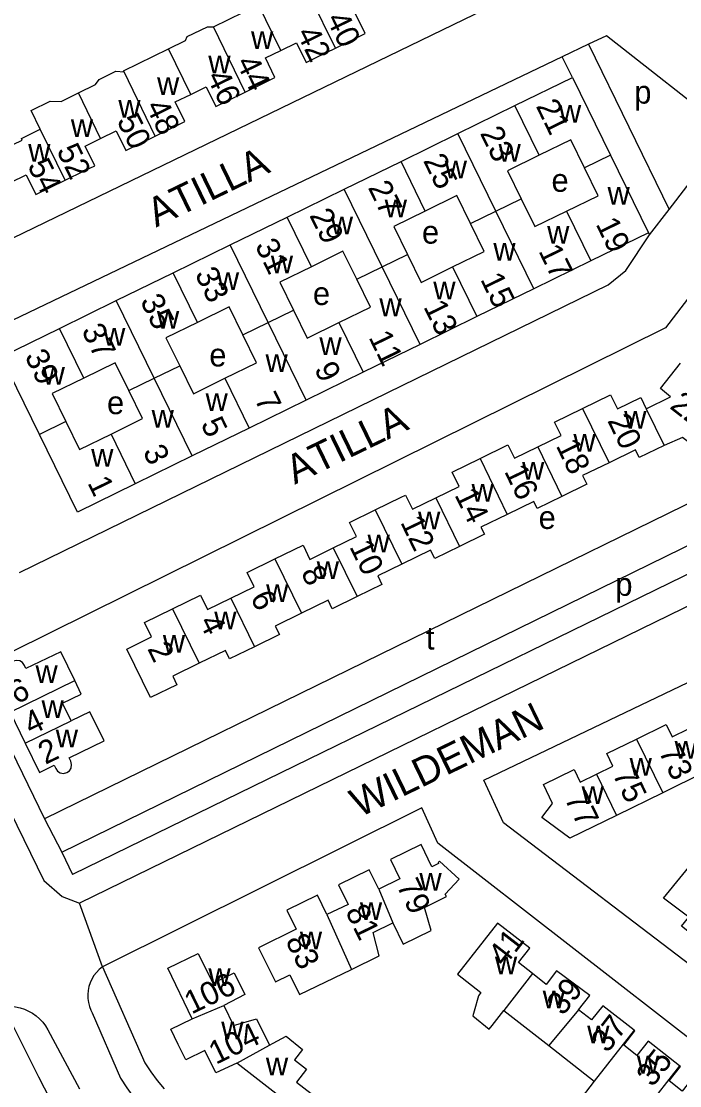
# Model space of a CAD drawing. Extents: x 159441 to 162086, y 388175 to 389787.
# Drawn here: x 161483.8 to 161598.1, y 388970.9 to 389155.6 of the extents above; entities that cross this region are included whole.
import ezdxf

# ---------------------------------------------------------------- set-up
doc = ezdxf.new("R2010")
doc.units = 0
for name, color, linetype in [('BLT_Basislijn', 7, 'Continuous'), ('BLT_Bebouwing', 7, 'Continuous'), ('BLT_Centroide', 7, 'Continuous'), ('BLT_Huisnummer', 7, 'Continuous'), ('BLT_Huisnummer_ tussenligend', 7, 'Continuous'), ('BLT_Onderverdeling_panden', 7, 'Continuous'), ('BLT_Straatnaam', 7, 'Continuous'), ('BLT_Vlakafsluiter', 7, 'Continuous')]:
    doc.layers.add(name, color=color, linetype=linetype)

msp = doc.modelspace()

# ---------------------------------------------------------------- linework, layer by layer
at = {"layer": 'BLT_Basislijn'}
for p, q in [((161582.29, 389151.56), (161577.7, 389149.36)), ((161582.29, 389151.56), (161596.3, 389122.92)), ((161579.53, 389145.82), (161577.7, 389149.36)), ((161592.9, 389118.5), (161596.3, 389122.92)), ((161592.71, 389118.87), (161592.9, 389118.5)), ((161564.11, 389023.88), (161624.74, 389052.92)), ((161567.55, 389016.49), (161564.11, 389023.88)), ((161553.38, 389019.06), (161497.93, 388991.48)), ((161556.12, 389012.95), (161553.38, 389019.06)), ((161669.17, 388938.91), (161567.55, 389016.49)), ((161661.19, 388931.3), (161556.12, 389012.95)), ((161497.93, 388991.48), (161505.28, 388974.84)), ((161486.88, 388972.34), (161480.76, 388984.58)), ((161496.17, 388983.5), (161501.07, 388972.14)), ((161488.48, 388980.54), (161493.94, 388970.29)), ((161505.28, 388974.84), (161506.33, 388973.28)), ((161506.33, 388973.28), (161507.44, 388971.77)), ((161507.44, 388971.77), (161508.62, 388970.3))]:
    msp.add_line(p, q, dxfattribs=at)
for points in [[(161431.36, 389153.61), (161423.06, 389149.55), (161446.94, 389100.8), (161584.9, 389167.69)], [(161596.3, 389122.92), (161606.62, 389136.37), (161585.4, 389153.05), (161582.29, 389151.56)], [(161577.7, 389149.36), (161465.43, 389095.59)], [(161623.83, 389139.1), (161595.65, 389102.37), (161475.36, 389042.81), (161487.87, 389017.18)], [(161647.2, 389120.24), (161615.5, 389079.64), (161487.87, 389017.18)], [(161483.54, 389059.9), (161585.71, 389109.81), (161588.75, 389112.33), (161592.9, 389118.5)], [(161490.89, 389011.37), (161618.3, 389073.8), (161620.71, 389075.73), (161652.36, 389115.82)], [(161655.94, 389112.75), (161625.53, 389073.89), (161617.95, 389068.61), (161492.72, 389007.49)], [(161618.18, 389063.15), (161493.93, 389002.52)], [(161471.42, 389039.92), (161487.78, 389006.47), (161490.93, 389003.71), (161493.93, 389002.52)], [(161487.87, 389017.18), (161490.89, 389011.37)], [(161490.89, 389011.37), (161492.72, 389007.49)], [(161497.93, 388991.48), (161497.37, 388991.02), (161496.88, 388990.52), (161496.46, 388989.96), (161496.09, 388989.36), (161495.8, 388988.72), (161495.59, 388988.05), (161495.45, 388987.37), (161495.39, 388986.67), (161495.41, 388985.97), (161495.51, 388985.28), (161495.69, 388984.6), (161495.94, 388983.95), (161496.17, 388983.5)], [(161480.76, 388984.58), (161481.28, 388984.63), (161482.07, 388984.62), (161482.86, 388984.54), (161483.63, 388984.37), (161484.38, 388984.12), (161485.1, 388983.81), (161485.79, 388983.42), (161486.44, 388982.96), (161487.03, 388982.44), (161487.57, 388981.86), (161488.05, 388981.23), (161488.48, 388980.54)], [(161500.72, 388954.39), (161499.17, 388955.75), (161497.67, 388957.17), (161496.22, 388958.65), (161494.84, 388960.18), (161493.51, 388961.77), (161492.24, 388963.41), (161491.05, 388965.09), (161489.91, 388966.82), (161488.85, 388968.59), (161487.85, 388970.4), (161486.88, 388972.34)], [(161501.07, 388972.14), (161502.18, 388970.49), (161503.35, 388968.89), (161504.58, 388967.33), (161505.88, 388965.83), (161507.24, 388964.38), (161508.65, 388962.99), (161510.12, 388961.65), (161511.2, 388960.73)]]:
    msp.add_lwpolyline(points, dxfattribs=at)
at = {"layer": 'BLT_Bebouwing'}
for p, q in [((161559.63, 389136.09), (161569.51, 389140.92)), ((161549.75, 389131.25), (161559.63, 389136.09)), ((161539.87, 389126.42), (161549.75, 389131.25)), ((161529.99, 389121.59), (161539.87, 389126.42)), ((161520.1, 389116.75), (161529.99, 389121.59)), ((161510.22, 389111.92), (161520.1, 389116.75)), ((161582.69, 389113.97), (161572.81, 389109.14)), ((161500.34, 389107.09), (161510.22, 389111.92)), ((161572.81, 389109.14), (161562.93, 389104.31)), ((161490.46, 389102.25), (161500.34, 389107.09)), ((161562.93, 389104.31), (161553.05, 389099.47)), ((161480.41, 389097.34), (161490.46, 389102.25)), ((161553.05, 389099.47), (161543.17, 389094.64)), ((161487, 389083.86), (161480.41, 389097.34)), ((161543.17, 389094.64), (161533.29, 389089.81)), ((161533.29, 389089.81), (161523.41, 389084.97)), ((161523.41, 389084.97), (161513.52, 389080.14)), ((161513.52, 389080.14), (161503.64, 389075.31)), ((161481.93, 389035.66), (161484.54, 389030.27)), ((161603.18, 389025.66), (161595.17, 389021.68)), ((161595.17, 389021.68), (161587.17, 389017.76)), ((161567.61, 388983.89), (161575.39, 388977.8)), ((161575.39, 388977.8), (161583.28, 388971.62))]:
    msp.add_line(p, q, dxfattribs=at)
for points in [[(161517.21, 389154.58), (161525.02, 389158.4)], [(161538.37, 389150.91), (161543.52, 389153.43), (161541.85, 389156.85), (161544.52, 389158.15)], [(161509.39, 389150.76), (161512.37, 389152.22), (161512.65, 389152.9), (161516.18, 389154.58), (161517.21, 389154.58)], [(161528.88, 389150.5), (161531.6, 389151.83), (161533.27, 389148.42), (161535.14, 389149.34), (161538.37, 389150.91)], [(161501.7, 389146.77), (161501.61, 389146.96), (161509.39, 389150.76)], [(161522.73, 389143.27), (161526.01, 389144.87), (161527.88, 389145.79), (161526.21, 389149.2), (161528.88, 389150.5)], [(161493.76, 389143.11), (161496.74, 389144.57), (161497.36, 389145.44), (161500.24, 389146.88), (161501.7, 389146.77)], [(161569.51, 389140.92), (161579.53, 389145.82)], [(161579.53, 389145.82), (161586.12, 389132.35)], [(161513.25, 389142.86), (161515.96, 389144.19), (161517.63, 389140.77), (161519.5, 389141.69), (161522.73, 389143.27)], [(161487.13, 389136.83), (161485.54, 389140.07), (161488.84, 389141.69), (161490.77, 389141.65), (161493.76, 389143.11)], [(161507.1, 389135.62), (161510.38, 389137.23), (161512.24, 389138.14), (161510.58, 389141.55), (161513.25, 389142.86)], [(161478.12, 389135.47), (161481.1, 389136.92), (161482.44, 389134.18), (161484.02, 389134.95), (161483.88, 389135.24), (161487.13, 389136.83)], [(161497.62, 389135.22), (161500.33, 389136.54), (161502, 389133.13), (161507.1, 389135.62)], [(161491.47, 389127.98), (161494.74, 389129.58), (161496.61, 389130.49), (161494.94, 389133.9), (161497.62, 389135.22)], [(161581.58, 389130.13), (161579.21, 389134.98), (161573.73, 389132.3)], [(161573.73, 389132.3), (161568.25, 389129.62), (161570.62, 389124.77)], [(161586.12, 389132.35), (161592.71, 389118.87)], [(161578.48, 389122.6), (161583.95, 389125.28), (161581.58, 389130.13)], [(161481.99, 389127.57), (161484.69, 389128.89), (161486.36, 389125.48), (161491.47, 389127.98)], [(161561.82, 389120.46), (161559.45, 389125.31), (161553.97, 389122.63)], [(161570.62, 389124.77), (161573, 389119.92), (161578.48, 389122.6)], [(161553.97, 389122.63), (161548.49, 389119.95), (161550.86, 389115.1)], [(161558.71, 389112.93), (161564.19, 389115.61), (161561.82, 389120.46)], [(161592.71, 389118.87), (161582.69, 389113.97)], [(161542.06, 389110.79), (161539.68, 389115.64), (161534.2, 389112.96)], [(161550.86, 389115.1), (161553.23, 389110.25), (161558.71, 389112.93)], [(161534.2, 389112.96), (161528.73, 389110.28), (161531.1, 389105.43)], [(161538.95, 389103.26), (161544.43, 389105.94), (161542.06, 389110.79)], [(161522.29, 389101.13), (161519.92, 389105.98), (161514.44, 389103.3)], [(161531.1, 389105.43), (161533.47, 389100.58), (161538.95, 389103.26)], [(161514.44, 389103.3), (161508.96, 389100.62), (161511.34, 389095.77)], [(161519.19, 389093.6), (161524.67, 389096.28), (161522.29, 389101.13)], [(161502.53, 389091.46), (161500.16, 389096.31), (161494.68, 389093.63)], [(161511.34, 389095.77), (161513.71, 389090.92), (161519.19, 389093.6)], [(161592.32, 389088.29), (161596.53, 389090.37), (161594.78, 389091.81), (161598.25, 389096.25)], [(161494.68, 389093.63), (161489.2, 389090.95), (161491.57, 389086.1)], [(161499.43, 389083.93), (161504.9, 389086.61), (161502.53, 389091.46)], [(161581.24, 389088.38), (161586.1, 389090.75), (161587.3, 389088.28), (161591.35, 389090.26), (161592.32, 389088.29)], [(161573.48, 389081.72), (161577.53, 389083.69), (161576.39, 389086.01), (161581.24, 389088.38)], [(161606.52, 389089.79), (161603.67, 389086.14), (161604.94, 389085.15), (161601.66, 389080.95), (161598.62, 389083.33), (161595.4, 389081.97)], [(161491.57, 389086.1), (161493.95, 389081.25), (161499.43, 389083.93)], [(161503.64, 389075.31), (161493.59, 389070.39), (161487, 389083.86)], [(161563.46, 389079.68), (161568.31, 389082.05), (161569.44, 389079.74), (161573.48, 389081.72)], [(161595.4, 389081.97), (161591.09, 389079.86), (161590.44, 389081.19), (161585.85, 389078.95)], [(161555.77, 389072.86), (161559.82, 389074.84), (161558.61, 389077.31), (161563.46, 389079.68)], [(161585.85, 389078.95), (161581.27, 389076.71), (161582, 389075.23), (161577.68, 389073.12)], [(161545.29, 389070.8), (161549.77, 389072.99), (161550.52, 389073.35), (161551.73, 389070.88), (161555.77, 389072.86)], [(161577.68, 389073.12), (161573.38, 389071.01), (161572.78, 389072.23), (161568.2, 389069.99)], [(161537.99, 389064.16), (161542.03, 389066.14), (161540.82, 389068.61), (161545.29, 389070.8)], [(161568.2, 389069.99), (161563.62, 389067.75), (161564.21, 389066.53), (161559.9, 389064.42)], [(161527.88, 389062.28), (161532.74, 389064.65), (161533.94, 389062.18), (161537.99, 389064.16)], [(161559.9, 389064.42), (161555.59, 389062.32), (161554.87, 389063.79), (161549.9, 389061.37)], [(161520.2, 389055.46), (161524.24, 389057.44), (161523.03, 389059.91), (161527.88, 389062.28)], [(161549.9, 389061.37), (161545.7, 389059.32), (161546.43, 389057.83), (161542.12, 389055.72)], [(161510.1, 389053.58), (161514.95, 389055.95), (161516.16, 389053.48), (161520.2, 389055.46)], [(161542.12, 389055.72), (161537.8, 389053.61), (161537.08, 389055.09), (161532.5, 389052.85)], [(161514.71, 389044.15), (161510.13, 389041.92), (161510.85, 389040.43), (161506.27, 389038.19), (161502.15, 389046.63), (161506.46, 389048.74), (161505.25, 389051.21), (161510.1, 389053.58)], [(161532.5, 389052.85), (161527.91, 389050.62), (161528.64, 389049.13), (161524.33, 389047.02)], [(161493.13, 389041.14), (161490.7, 389046.16), (161484.65, 389043.24), (161484.39, 389043.78), (161484.05, 389044.27), (161483.6, 389044.56), (161483.02, 389044.66), (161482.43, 389044.51), (161481.92, 389044.1), (161481.66, 389043.57), (161481.63, 389043.01), (161481.79, 389042.52), (161482.05, 389041.98), (161479.48, 389040.73)], [(161524.33, 389047.02), (161520.01, 389044.91), (161519.29, 389046.39), (161514.71, 389044.15)], [(161492.51, 389034.15), (161491.01, 389037.24), (161494.25, 389038.82), (161493.13, 389041.14)], [(161484.54, 389030.27), (161486.99, 389025.2), (161489.56, 389026.45), (161489.82, 389025.91), (161490.13, 389025.45), (161490.58, 389025.15), (161491.15, 389025.03), (161491.78, 389025.18), (161492.21, 389025.49), (161492.49, 389025.94), (161492.59, 389026.57), (161492.42, 389027.18), (161492.16, 389027.72), (161498.22, 389030.67), (161495.75, 389035.74), (161492.51, 389034.15)], [(161590.61, 389031), (161595.76, 389033.53), (161596.83, 389031.37), (161599.66, 389032.76)], [(161583.67, 389024.93), (161586.51, 389026.32), (161585.45, 389028.47), (161590.61, 389031)], [(161587.17, 389017.76), (161579.05, 389013.79), (161574.2, 389017.37), (161576.04, 389019.83), (161574.46, 389023.09), (161579.78, 389025.7), (161580.83, 389023.54), (161583.67, 389024.93)], [(161548.34, 388999.12), (161550.14, 388995.42), (161554.98, 388997.79), (161553.83, 389001.8), (161557.63, 389003.66), (161557.41, 389004.1), (161559.83, 389006.69), (161556.4, 389009.82), (161556.18, 389009.59), (161556.27, 389009.41), (161555.1, 389008.84), (161553.22, 389012.69), (161547.9, 389010.08), (161549.55, 389006.74), (161545.89, 389004.95)], [(161602.29, 388995.48), (161598.42, 388998.53), (161599.7, 389000.09), (161595.32, 389003.42), (161602, 389011.58), (161606.38, 389008.15), (161607.25, 389009.27), (161610.91, 389006.44)], [(161545.89, 389004.95), (161544.24, 389008.29), (161538.91, 389005.69), (161540.59, 389002.32), (161536.88, 389000.54)], [(161536.88, 389000.54), (161535.26, 389003.92), (161529.96, 389001.29), (161531.56, 388997.99), (161525.04, 388994.8), (161527.94, 388988.87), (161530.48, 388990.11), (161532.16, 388986.65), (161541.14, 388991.04)], [(161541.14, 388991.04), (161545.98, 388993.4), (161544.93, 388997.45), (161548.34, 388999.12)], [(161572.56, 388990.31), (161570.12, 388992.22), (161572.08, 388994.69), (161566.49, 388999.07), (161559.53, 388990.22), (161563.61, 388987.03), (161563.17, 388986.46), (161562.46, 388983.78), (161562.23, 388982.96), (161565.07, 388980.67), (161565.59, 388981.32), (161567.61, 388983.89)], [(161513.48, 388982.48), (161509.26, 388991.22), (161514.57, 388993.81), (161517.09, 388988.65), (161520.77, 388990.44), (161522.62, 388986.65), (161518.98, 388984.76)], [(161580.55, 388984.04), (161582.5, 388986.52), (161576.71, 388990.77), (161574.96, 388988.43), (161572.56, 388990.31)], [(161518.98, 388984.76), (161520.68, 388981.29), (161524.68, 388982.43), (161526.9, 388977.91)], [(161590.23, 388980.47), (161584.77, 388984.73), (161582.83, 388982.26), (161580.55, 388984.04)], [(161511.09, 388978.01), (161509.79, 388980.67), (161513.48, 388982.48)], [(161526.9, 388977.91), (161527.55, 388978.26), (161529.82, 388979.47)], [(161529.82, 388979.47), (161532.65, 388977.12), (161531.27, 388975.36), (161533.37, 388973.72), (161531.62, 388971.48), (161536.17, 388967.93)], [(161598.09, 388974.3), (161592.64, 388978.57), (161590.7, 388976.09), (161588.4, 388977.89), (161590.35, 388980.37), (161590.23, 388980.47)], [(161521.27, 388974.74), (161517.62, 388973.07), (161515.72, 388976.97), (161512.4, 388975.34), (161511.09, 388978.01)], [(161529.98, 388960.03), (161525.26, 388963.73), (161529.07, 388968.68), (161521.27, 388974.74)], [(161605.96, 388968.13), (161600.5, 388972.39), (161598.56, 388969.92), (161596.29, 388971.71), (161598.23, 388974.18), (161598.09, 388974.3)], [(161583.28, 388971.62), (161580.41, 388967.95), (161583.53, 388965.51), (161586.13, 388965.77), (161587.88, 388968.01), (161591.15, 388965.45)]]:
    msp.add_lwpolyline(points, dxfattribs=at)
at = {"layer": 'BLT_Onderverdeling_panden'}
for p, q in [((161538.37, 389150.91), (161532.83, 389162.22)), ((161528.88, 389150.5), (161525.02, 389158.4)), ((161522.73, 389143.27), (161517.21, 389154.58)), ((161513.25, 389142.86), (161509.39, 389150.76)), ((161507.1, 389135.62), (161501.7, 389146.77)), ((161497.62, 389135.22), (161493.76, 389143.11)), ((161573.73, 389132.3), (161569.51, 389140.92)), ((161491.47, 389127.98), (161487.13, 389136.83)), ((161566.22, 389122.61), (161559.63, 389136.09)), ((161553.97, 389122.63), (161549.75, 389131.25)), ((161586.12, 389132.35), (161581.58, 389130.13)), ((161546.46, 389112.95), (161539.87, 389126.42)), ((161566.22, 389122.61), (161570.62, 389124.77)), ((161534.2, 389112.96), (161529.99, 389121.59)), ((161561.82, 389120.46), (161566.22, 389122.61)), ((161572.81, 389109.14), (161566.22, 389122.61)), ((161578.48, 389122.6), (161582.69, 389113.97)), ((161526.7, 389103.28), (161520.1, 389116.75)), ((161546.46, 389112.95), (161550.86, 389115.1)), ((161542.06, 389110.79), (161546.46, 389112.95)), ((161553.05, 389099.47), (161546.46, 389112.95)), ((161558.71, 389112.93), (161562.93, 389104.31)), ((161514.44, 389103.3), (161510.22, 389111.92)), ((161506.93, 389093.61), (161500.34, 389107.09)), ((161526.7, 389103.28), (161531.1, 389105.43)), ((161522.29, 389101.13), (161526.7, 389103.28)), ((161533.29, 389089.81), (161526.7, 389103.28)), ((161538.95, 389103.26), (161543.17, 389094.64)), ((161494.68, 389093.63), (161490.46, 389102.25)), ((161506.93, 389093.61), (161511.34, 389095.77)), ((161502.53, 389091.46), (161506.93, 389093.61)), ((161513.52, 389080.14), (161506.93, 389093.61)), ((161519.19, 389093.6), (161523.41, 389084.97)), ((161581.24, 389088.38), (161585.85, 389078.95)), ((161592.32, 389088.29), (161595.4, 389081.97)), ((161491.57, 389086.1), (161487, 389083.86)), ((161499.43, 389083.93), (161503.64, 389075.31)), ((161573.48, 389081.72), (161577.68, 389073.12)), ((161563.46, 389079.68), (161568.2, 389069.99)), ((161555.77, 389072.86), (161559.9, 389064.42)), ((161545.29, 389070.8), (161549.9, 389061.37)), ((161537.99, 389064.16), (161542.12, 389055.72)), ((161527.88, 389062.28), (161532.5, 389052.85)), ((161520.2, 389055.46), (161524.33, 389047.02)), ((161510.1, 389053.58), (161514.71, 389044.15)), ((161481.93, 389035.66), (161493.13, 389041.14)), ((161484.54, 389030.27), (161492.51, 389034.15)), ((161590.61, 389031), (161595.17, 389021.68)), ((161583.67, 389024.93), (161587.17, 389017.76)), ((161545.89, 389004.95), (161548.34, 388999.12)), ((161536.88, 389000.54), (161541.14, 388991.04)), ((161572.56, 388990.31), (161567.61, 388983.89)), ((161513.48, 388982.48), (161518.98, 388984.76)), ((161580.55, 388984.04), (161575.39, 388977.8)), ((161590.23, 388980.47), (161583.28, 388971.62)), ((161521.27, 388974.74), (161526.9, 388977.91)), ((161598.09, 388974.3), (161591.15, 388965.45))]:
    msp.add_line(p, q, dxfattribs=at)
at = {"layer": 'BLT_Vlakafsluiter'}
msp.add_line((161497.93, 388991.48), (161493.93, 389002.52), dxfattribs=at)

# ---------------------------------------------------------------- texts
at = {"layer": 'BLT_Centroide'}
for s, p in [('w', (161523.72, 389150.75)), ('w', (161516.31, 389146.5)), ('w', (161507.41, 389142.78)), ('p', (161590.23, 389141.27)), ('w', (161500.69, 389138.84)), ('w', (161577.16, 389137.97)), ('w', (161492.45, 389135.47)), ('w', (161485.05, 389131.19)), ('w', (161566.67, 389131.19)), ('w', (161557.33, 389128.28)), ('e', (161575.86, 389125.97)), ('w', (161585.59, 389123.73)), ('w', (161546.92, 389121.52)), ('w', (161537.56, 389118.59)), ('e', (161553.39, 389116.97)), ('w', (161575.11, 389116.97)), ('w', (161565.77, 389114.03)), ('w', (161527.16, 389111.84)), ('w', (161517.8, 389108.94)), ('e', (161534.46, 389106.32)), ('w', (161555.35, 389107.28)), ('w', (161546, 389104.38)), ('w', (161507.39, 389102.19)), ('w', (161498.05, 389099.28)), ('w', (161535.59, 389097.62)), ('e', (161516.48, 389095.66)), ('w', (161526.23, 389094.7)), ('w', (161487.55, 389092.47)), ('e', (161498.73, 389087.38)), ('w', (161515.83, 389087.94)), ('w', (161506.47, 389085.03)), ('w', (161588.48, 389084.84)), ('w', (161579.67, 389080.86)), ('w', (161495.98, 389078.25)), ('w', (161570.76, 389076.03)), ('w', (161561.98, 389072.2)), ('w', (161552.71, 389067.38)), ('e', (161573.63, 389067.46)), ('w', (161543.94, 389063.38)), ('w', (161535.12, 389058.75)), ('p', (161586.95, 389055.86)), ('w', (161526.34, 389054.77)), ('w', (161517.34, 389050.06)), ('t', (161554.07, 389046.53)), ('w', (161508.42, 389046)), ('w', (161486.31, 389040.75)), ('w', (161487.36, 389034.66)), ('w', (161489.83, 389029.56)), ('w', (161597.23, 389027.59)), ('w', (161589.42, 389024.64)), ('w', (161581.09, 389019.75)), ('w', (161552.94, 389004.67)), ('w', (161542.61, 388999.62)), ('w', (161532.19, 388994.52)), ('w', (161566.05, 388990.19)), ('w', (161516.32, 388988.16)), ('w', (161574.34, 388984.28)), ('w', (161518.55, 388978.88)), ('w', (161582.06, 388978.19)), ('w', (161526.3, 388972.63)), ('w', (161590.69, 388972.97))]:
    msp.add_text(s, height=4, dxfattribs=at).set_placement(p)
at = {"layer": 'BLT_Huisnummer'}
for s, rotation, p in [('42', 296.0697, (161531.55, 389153.5)), ('46', 296.0697, (161515.93, 389145.94)), ('21', 296.0645, (161573.09, 389140.86)), ('50', 296.0697, (161500.35, 389138.34)), ('54', 296.0697, (161484.85, 389130.54)), ('27', 296.0645, (161543.95, 389126.73)), ('19', 296.0645, (161583.48, 389120.37)), ('31', 296.0645, (161524.34, 389116.66)), ('35', 296.0645, (161504.41, 389107.04)), ('13', 296.0645, (161553.58, 389106.04)), ('39', 296.0645, (161484.37, 389097.46)), ('9', 296.0645, (161534.62, 389095.27)), ('22', 322.0058, (161596.21, 389088.52)), ('5', 296.0645, (161514.92, 389085.69)), ('18', 296.0059, (161576.56, 389081.92)), ('1', 296.0645, (161495.27, 389075.48)), ('14', 296.0059, (161558.97, 389073.4)), ('10', 296.0059, (161540.73, 389064.4)), ('6', 296.0059, (161523.53, 389055.61)), ('2', 296.0059, (161505.67, 389046.69)), ('6', 26.0626, (161482.99, 389036.98)), ('2', 26.0626, (161488.03, 389026.51)), ('77', 296.0725, (161578.06, 389020.7)), ('79', 296.0725, (161548.9, 389005.59)), ('83', 296.0725, (161529.62, 388996.03)), ('41', 52.266, (161567.7, 388991.34)), ('106', 25.8629, (161513.39, 388983.18)), ('37', 52.266, (161585.58, 388976.38))]:
    msp.add_text(s, height=4, rotation=rotation, dxfattribs=at).set_placement(p)
at = {"layer": 'BLT_Huisnummer_ tussenligend'}
for s, rotation, p in [('40', 296.0697, (161536.7, 389156)), ('44', 296.0697, (161521.05, 389148.43)), ('48', 296.0697, (161505.36, 389140.81)), ('23', 296.0645, (161563.4, 389136.15)), ('52', 296.0697, (161489.9, 389133.13)), ('25', 296.0645, (161553.53, 389131.39)), ('29', 296.0645, (161533.79, 389121.9)), ('17', 296.0645, (161573.54, 389115.71)), ('33', 296.0645, (161513.9, 389111.72)), ('15', 296.0645, (161563.45, 389110.79)), ('37', 296.0645, (161494.23, 389101.92)), ('11', 296.0645, (161544.06, 389100.74)), ('7', 296.0645, (161524.26, 389090)), ('20', 296.0059, (161585.5, 389086.26)), ('3', 296.0645, (161504.87, 389080.9)), ('16', 296.0059, (161567.59, 389077.48)), ('12', 296.0059, (161549.57, 389068.62)), ('8', 296.0059, (161532.31, 389059.93)), ('4', 296.0059, (161514.63, 389051.38)), ('4', 26.0626, (161485.53, 389031.6)), ('73', 296.0725, (161594.39, 389028.86)), ('75', 296.0725, (161586.38, 389024.93)), ('81', 296.0725, (161540.02, 389001.11)), ('39', 52.266, (161577.87, 388982.84)), ('104', 25.8629, (161517.62, 388974.46)), ('35', 52.266, (161593.41, 388970.46))]:
    msp.add_text(s, height=4, rotation=rotation, dxfattribs=at).set_placement(p)
at = {"layer": 'BLT_Straatnaam'}
for s, rotation, p in [('ATILLA', 25.8394, (161507.24, 389119.74)), ('ATILLA', 25.8394, (161531.31, 389075.13)), ('WILDEMAN', 25.839, (161542.53, 389017.33))]:
    msp.add_text(s, height=5, rotation=rotation, dxfattribs=at).set_placement(p)

doc.saveas('drawing.dxf')
